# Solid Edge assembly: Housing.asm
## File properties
Title: Housing Assembly
Last saved by: Dan
Revision: 105
Project Name: Piston Pump P52
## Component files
Housing.par
Check Valve.asm
Bush PAP 2830 P10.par
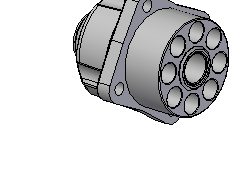
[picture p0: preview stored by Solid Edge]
